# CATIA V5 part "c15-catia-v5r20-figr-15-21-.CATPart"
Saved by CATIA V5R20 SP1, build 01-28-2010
Part number: Part1
Bounding box of the stored display mesh (mm): x -81.56 to 85.56, y -36.965 to 25.965, z 0 to 42
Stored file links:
  D:\v5_r20\psrt_files_downloaded\c15\c15-catia-v5r20-figr-15-21-.CATPart
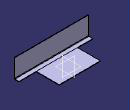
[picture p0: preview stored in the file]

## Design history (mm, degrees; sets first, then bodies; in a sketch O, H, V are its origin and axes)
SheetMetalParameters1: Thickness 1, BendRadius 1, KFactor 0.325257 {= log(min(100,max(20*SheetMetalParameters1.BendRadius,SheetMetalParameters1.Thickness)/SheetMetalParameters1.Thickness))/log(100)/2}, ReliefRadialLength 1, ReliefAxialLength 2, MinimumBendRadius 0
Body1 (main body)
  Sketch1 on xy-plane, origin (0, 0, 0), H (1, 0, 0), V (0, 1, 0)
    line L1 (-46.5596, 25.9646) -> (46.5596, 25.9646)
    line L2 (46.5596, 25.9646) -> (46.5596, -25.9646)
    line L3 (46.5596, -25.9646) -> (-46.5596, -25.9646)
    line L4 (-46.5596, -25.9646) -> (-46.5596, 25.9646)
    horizontal: L1 H, L3 H
    vertical: L2 V, L4 V
    symmetry: L1 L3 H, L4 L2 V
  Wall1: Thickness 1, Profile Sketch1
  d_NewWallOnEdge1: NewWallOnEdge_Edge edge [face of Wall1 | face of Wall1], NewWallOnEdge_Length 42, NewWallOnEdge_HeightLimitOffset 0, NewWallOnEdge_WidthOffset1 39, NewWallOnEdge_WidthOffset2 35, NewWallOnEdge_Angle 90, NewWallOnEdge_BendRadiusValue 1 {= SheetMetalParameters1.BendRadius}, NewWallOnEdge_BendTable SheetMetalParameters1, KFacteur 0.325257 {= log(min(100,max(20*d_NewWallOnEdge1.Radius,SheetMetalParameters1.Thickness)/SheetMetalParameters1.Thickness))/log(100)/2}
